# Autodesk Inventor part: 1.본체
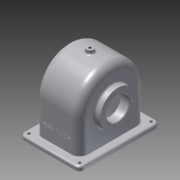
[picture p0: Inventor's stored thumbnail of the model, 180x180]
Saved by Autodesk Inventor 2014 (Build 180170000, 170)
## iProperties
Created: 2016-01
Part Number: 1.본체
Material: 알루미늄 6061
Document SubType Name: Modeling
Designer: SCD-A13
Density: 2.71 g/cm^3
Appearance: 알루미늄 - 평지
Mass: 808.189 g
Surface Area: 998.158 cm^2
Volume: 298.225 cm^3
Author: SCD-A13
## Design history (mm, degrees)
sketch "스케치1"
  geometry: L1 (-52, 70)-(52, 70); L2 (52, 70)-(52, -70); L3 (52, -70)-(-52, -70); L4 (-52, -70)-(-52, 70); 3 further points
  constraints: 8 end point, 2 midpoint, 2 parallel, 1 horizontal, 1 horizontal alignment, 1 perpendicular, 1 vertical alignment
  dimensions: "d0" = 140 distance of L3.end L1.start; "d1" = 104 distance of L1.start L1.end
extrude "돌출1" new body sketch "스케치1" distance "d2" = 7; taper "d3" = 0 deg
fillet "모깎기1" dims "d4" = 8
sketch "스케치3"
  geometry: A1 r 8 centre (-44, 62) between (-44, 70) and (-52, 62) reference; A2 r 8 centre (-44, -62) between (-52, -62) and (-44, -70) reference; A3 r 8 centre (44, -62) between (44, -70) and (52, -62) reference; A4 r 8 centre (44, 62) between (52, 62) and (44, 70) reference; 1 further point
hole "구멍1" sketch "스케치3" at (44, 62), (-44, 62), (-44, -62), (44, -62) diameter "d9" = 5; stored, may be unused: countersink angle "d13" = 90 deg, drill point angle "d15" = 118 deg; dims "d10" = 6, "d11" = 4, "d12" = 2, "d14" = 8
sketch "스케치7"
  geometry: L1 (-57, 0)-(57, 0); L2 (57, 0)-(57, 64); L3 (57, 64)-(-57, 64); L4 (-57, 64)-(-57, 0); L5 (-62, 0)-(62, 0) reference; A1 r 57 centre (0, 64) between (57, 64) and (-57, 64); 3 further points
  constraints: 8 end point, 3 midpoint, 2 parallel, 2 point on circle, 1 centre point, 1 coincident, 1 collinear, 1 horizontal, 1 perpendicular
  dimensions: "d24" = 64 distance of L3.end L1.start; "d25" = 114 distance of L2.end L3.end
extrude "돌출5" join sketch "스케치7" stored distance "d26" = 77; taper "d27" = 0 deg
sketch "스케치8"
  geometry: C1 r 31 at (-60, 0); 1 further point
  constraints: 1 centre point, 1 horizontal alignment
  dimensions: "d28" = 62 diameter of C1; "d29" = 60 distance of point (0, 0) C1.centre
extrude "돌출6" join sketch "스케치8" distance "d30" = 10; taper "d31" = 0 deg
sketch "스케치9"
  geometry: L1 (-51, 64)-(51, 64); L2 (51, 64)-(51, 0); L3 (51, 0)-(-51, 0); L4 (-51, 0)-(-51, 64); A1 r 57 centre (0, 64) between (57, 64) and (-57, 64) reference; A2 r 51 centre (0, 64) between (51, 64) and (-51, 64); 1 further point
  constraints: 8 end point, 2 parallel, 2 point on circle, 1 centre point, 1 horizontal, 1 perpendicular
  dimensions: "d32" = 6 radial gap between concentric circles of A1 A2; "d33" = 64 distance of L3.end L1.start; "d34" = 102 distance of L2.end L3.end
extrude "돌출7" cut sketch "스케치9" stored distance "d35" = 67; taper "d36" = 0 deg
sketch "스케치10"
  geometry: L1 (-48.5, 91)-(-48.5, 29) reference; L2 (-45.953, 60.779)-(38.5, 60.779); L3 (33.5, 100.527)-(19.5, 88.779); L4 (19.5, 88.779)-(19.5, 60.779); L5 (33.5, 100.527)-(33.5, 60.779); L6 (33.5, 64)-(33.5, 115) reference; L7 (38.5, 64)-(38.5, 7) reference; 1 further point
  constraints: 8 end point, 3 perpendicular, 3 point on line, 1 collinear
  dimensions: "d37" = 50 deg angle of L4 L3; "d38" = 28 distance of L3.end L4.end; "d39" = 19 distance of L2.end L4.end
revolve "회전1" sketch "스케치10" stored, may be unused: angle "d40" = 90 deg
hole "구멍2" diameter "d45" = 40; stored, may be unused: countersink angle "d49" = 90 deg, drill point angle "d51" = 118 deg; dims "d43" = 10, "d44" = 10, "d46" = 6, "d47" = 4, "d48" = 2, "d50" = 8
sketch "스케치13"
  geometry: L1 (38.5, 80)-(38.5, 40) reference; L2 (19.5, 40)-(19.5, 80) reference; L3 (38.5, 60)-(19.5, 60); L4 (38.5, 98.195)-(35.5, 95.678); L5 (35.5, 95.678)-(35.5, 60); L6 (19.5, 88.779)-(33.5, 100.527) reference; L7 (38.5, 98.195)-(38.5, 60); L8 (38.5, 64)-(38.5, 121) reference; 1 further point
  constraints: 8 end point, 2 midpoint, 2 point on line, 1 collinear, 1 parallel, 1 perpendicular
  dimensions: "d59" = 5 distance between parallel lines of L4 L6; "d60" = 3 distance between parallel lines of L5 L1; "d61" = 38.19501 distance of L4.start L7.end
revolve "회전2" sketch "스케치13" stored, may be unused: angle "d62" = 90 deg
node "작업 평면2"
  node "작업 평면1"
sketch "스케치14"
  geometry: C1 r 6 at (0, 0); 1 further point
  constraints: 1 centre point, 1 coincident
  dimensions: "d64" = 12 diameter of C1
extrude "돌출8" join sketch "스케치14" stored distance "d65" = 67; taper "d66" = 0 deg
hole "구멍3" diameter "d69" = 4.459; stored, may be unused: countersink angle "d73" = 90 deg, drill point angle "d75" = 118 deg; dims "d70" = 6, "d71" = 4, "d72" = 2, "d74" = 8, "d106" = 10, "d107" = 10
sketch "스케치15"
  geometry: L1 (60, 62)-(60, -62) reference; C1 r 20 at (0, 0) reference; 3 further points
  constraints: 1 horizontal alignment, 1 midpoint
  dimensions: "d76" = 24 distance of point (-24, 0) C1.centre
hole "구멍4" sketch "스케치15" at (-24, 0) diameter "d77" = 2.459; stored, may be unused: countersink angle "d81" = 90 deg, drill point angle "d83" = 118 deg; dims "d78" = 6, "d79" = 4, "d80" = 2, "d82" = 8
sketch "스케치16"
  geometry: L1 (0, -62)-(0, 62) reference; C1 r 38.195 at (60, 0) reference; 3 further points
  constraints: 1 horizontal alignment, 1 midpoint
  dimensions: "d87" = 28 distance of C1.centre point (88, 0)
hole "구멍5" sketch "스케치16" at (88, 0) diameter "d88" = 2.459; stored, may be unused: countersink angle "d92" = 90 deg, drill point angle "d94" = 118 deg; dims "d89" = 7, "d90" = 4, "d91" = 2, "d93" = 9
fillet "모깎기2" dims "d98" = 14
fillet "모깎기3" dims "d99" = 9
fillet "모깎기4" dims "d100" = 3
fillet "모깎기5" dims "d101" = 1
fillet "모깎기6" dims "d102" = 3
chamfer "모따기1" distance "d103" = 1; stored, may be unused: second distance "d104" = 2, angle "d105" = 45 deg
sketch "스케치17"
  geometry: L1 (68.5, -64)-(-19.5, -64) reference; 3 further points
  constraints: 1 midpoint, 1 vertical alignment, 1 other
  dimensions: "d108" = 30 distance from line of point (24.5, -34) L1
feature "엠보싱1" sketch "스케치17" dims "d0" = 140, "d1" = 104, "d13" = 90 deg, "d109" = 0.5, "d110" = 0
node "솔리드1"
pattern_circular "원형 패턴1" dims angle "d85" = 360 deg
pattern_circular "원형 패턴2" dims angle "d96" = 360 deg
other parameters: "d63" = 6
